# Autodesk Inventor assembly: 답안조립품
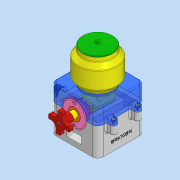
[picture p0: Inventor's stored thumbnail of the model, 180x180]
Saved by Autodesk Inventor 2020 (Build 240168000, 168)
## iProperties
Created: 2022-03
Part Number: 답안조립품
Document SubType Name: Assembly
Designer: Administrator
Author: Administrator
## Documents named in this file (11)
- C:\Users\Administrator\Desktop\720306V1010\답안조립품.iam
- C:\Users\Administrator\Desktop\720306V1010\본체.ipt
- C:\Users\Administrator\Desktop\720306V1010\본체커버.ipt
- C:\Users\Administrator\Desktop\720306V1010\핸들축.ipt
- C:\Users\Administrator\Desktop\720306V1010\앞커버.ipt
- C:\Users\Administrator\Desktop\720306V1010\베어링 부시.ipt
- C:\Users\Administrator\Desktop\720306V1010\용기.ipt
- C:\Users\Administrator\Desktop\720306V1010\용기캡.ipt
- C:\Users\Administrator\Desktop\720306V1010\핸들.ipt
- C:\Users\Administrator\Desktop\720306V1010\볼트 M3x12.ipt
- C:\Users\Administrator\Desktop\720306V1010\볼트 M4x12.ipt
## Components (2 placed, 2 different names)
1. 핸들축:1
2. 핸들:1
